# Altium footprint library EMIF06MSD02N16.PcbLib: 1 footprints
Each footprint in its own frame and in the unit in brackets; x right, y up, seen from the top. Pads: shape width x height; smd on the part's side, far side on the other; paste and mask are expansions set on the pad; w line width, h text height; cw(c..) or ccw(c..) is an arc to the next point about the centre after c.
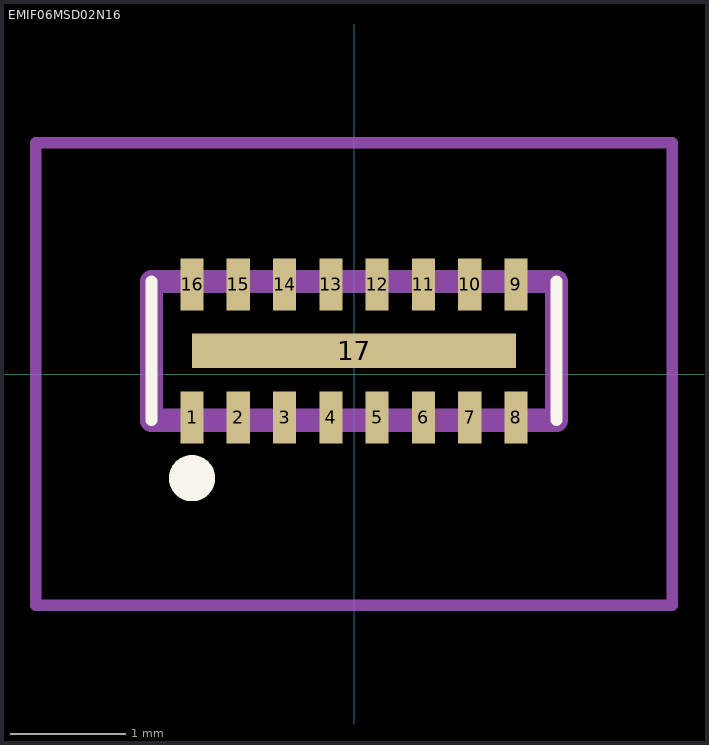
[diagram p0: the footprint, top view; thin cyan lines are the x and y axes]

## EMIF06MSD02N16 [mm]
pads (17):
  rect 0.2x0.45 smd: 1(-1.4,-0.375) 2(-1,-0.375) 3(-0.6,-0.375) 4(-0.2,-0.375) 5(0.2,-0.375) 6(0.6,-0.375) 7(1,-0.375) 8(1.4,-0.375) 9(1.4,0.775) 10(1,0.775) 11(0.6,0.775) 12(0.2,0.775) 13(-0.2,0.775) 14(-0.6,0.775) 15(-1,0.775) 16(-1.4,0.775)
  rect 2.8x0.3 smd: 17(0,0.2)
Top Overlay:
  lines w0.1: -1.75,-0.4 -1.75,0.8 ; 1.75,-0.4 1.75,0.8
  lines w0.2: -1.5,-0.9 -1.5,-0.9 ; -1.5,-0.9 cw(c-1.4,-0.9) -1.3,-0.9 ; -1.5,-0.9 ccw(c-1.4,-0.9) -1.3,-0.9 ; -1.3,-0.9 -1.3,-0.9
Mechanical 15:
  lines w0.2: -1.75,-0.4 1.75,-0.4 1.75,0.8 -1.75,0.8 -1.75,-0.4
Mechanical 20:
  lines w0.1: -2.75,-2 2.75,-2 2.75,2 -2.75,2 -2.75,-2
